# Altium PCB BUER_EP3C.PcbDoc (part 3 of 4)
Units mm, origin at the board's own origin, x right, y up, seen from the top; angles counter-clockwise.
Board outline 150 x 80 mm, 2 copper layers (Top Layer, Bottom Layer), stack 1.571 mm thick; 295 components, 180 nets, 1344 pads, 488 vias.
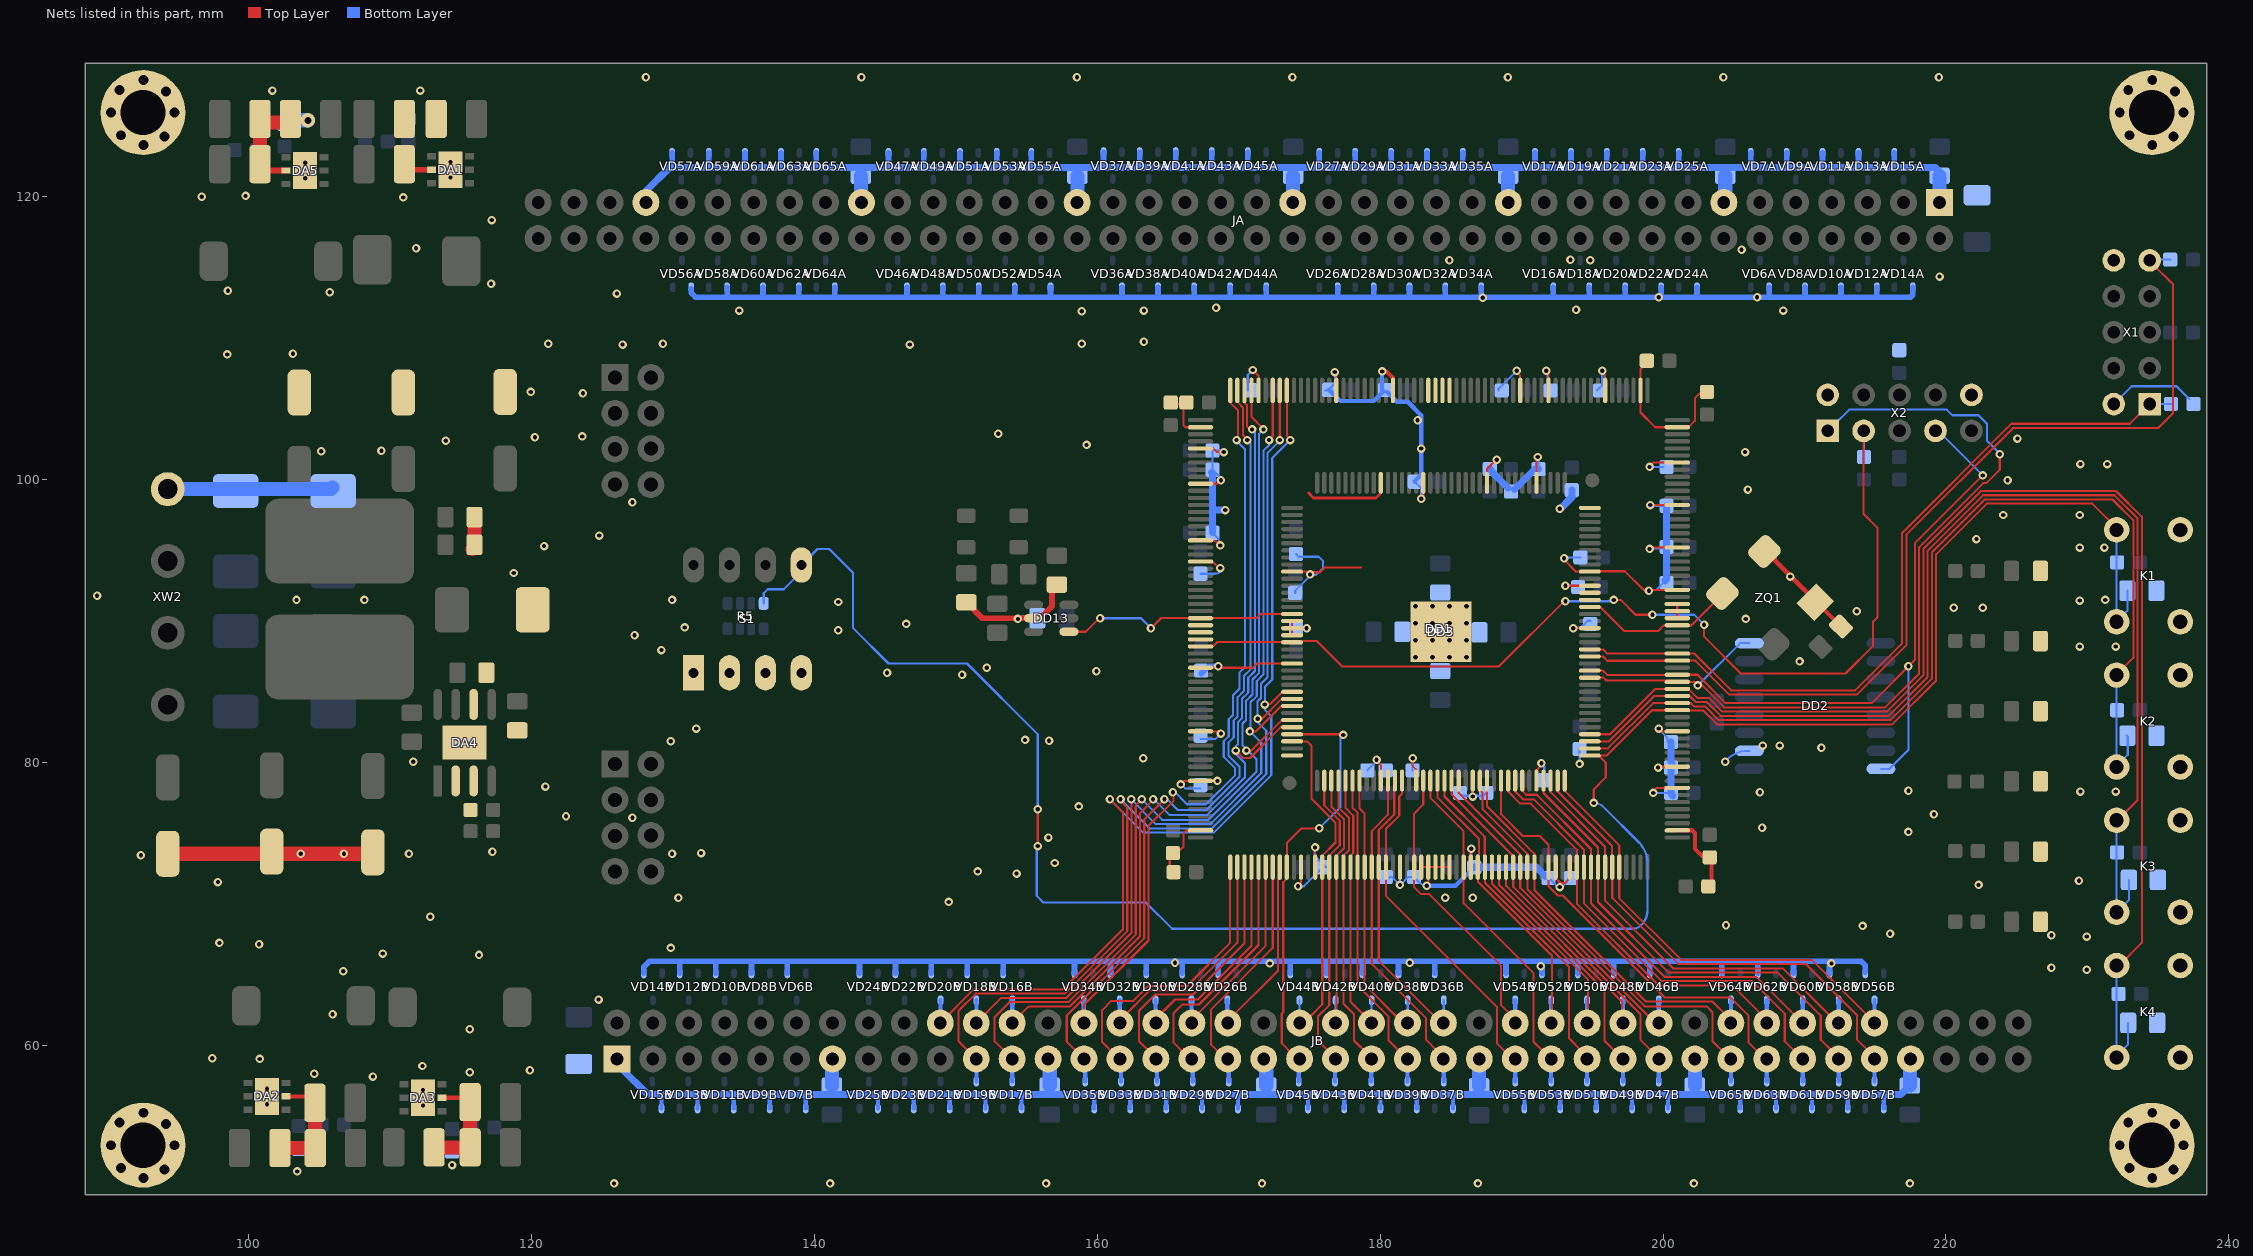
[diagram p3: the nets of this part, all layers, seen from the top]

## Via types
v1: diameter 0.6, hole 0.3, Top Layer to Bottom Layer, tented both sides, 413 vias
v2: diameter 1.4, hole 0.7, Top Layer to Bottom Layer, 32 vias
v3: diameter 1, hole 0.5, Top Layer to Bottom Layer, tented both sides, 19 vias
v4: diameter 0.66, hole 0.33, Top Layer to Bottom Layer, tented top, 16 vias
v5: diameter 0.6, hole 0.3, Top Layer to Bottom Layer, 8 vias

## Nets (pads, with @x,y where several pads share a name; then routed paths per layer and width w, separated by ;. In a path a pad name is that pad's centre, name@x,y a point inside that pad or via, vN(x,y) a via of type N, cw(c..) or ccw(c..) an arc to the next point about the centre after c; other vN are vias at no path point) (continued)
B15: DD1.112 DD3.99 JB.20 VD20B.3 | length 71
  Top Layer w0.15: JB.20@148.91,61.59 151.285,63.965 157.579,63.965 161.825,68.211 161.825,76.475 v1@161,77.3 ; v1@171.9,84.15 172.25,84.15 173.1,85 DD3.99@173.775,85 ; DD1.112@173.406,106.307 173.406,103.094 v1@173.7,102.8
  Bottom Layer w0.15: v1@160.925,77.375 163.25,75.05 168.238,75.05 172.3,79.112 172.3,83.278 171.875,83.703 171.875,85.375 172.375,85.875 172.375,101.525 v1(173.65,102.8)
  Bottom Layer w0.3: JB.20@148.85,61.75 148.925,61.825 VD20B.3@148.925,63.2
  other v1: 160.9,77.4 171.85,84.1
B16: DD1.113 DD3.100 JB.21 VD19B.3 | length 72.9
  Top Layer w0.15: JB.21@151.45,59.05 150.2,60.3 150.2,62.45 151.415,63.665 157.703,63.665 162.125,68.087 162.125,76.825 161.75,77.2 v1@161.75,77.4 ; v1(171.35,83.1) 171.65,83.1 173.05,84.5 DD3.100@173.775,84.5 ; v1@172.906,102.856 DD1.113@172.906,106.307
  Bottom Layer w0.15: v1@161.7,77.35 163.7,75.35 168.113,75.35 171.95,79.187 171.95,82.253 171.325,82.878 171.325,84.317 171.575,84.567 171.575,85.575 172.05,86.05 172.05,101.9 172.9,102.75 v1(172.9,102.8)
  Bottom Layer w0.3: VD19B.3@151.462,57.45 151.462,58.862 JB.21@151.6,59
  other v1: 161.65,77.4
B17: DD1.114 DD3.101 JB.22 VD18B.3 | length 67.8
  Top Layer w0.15: JB.22@151.45,61.59 153.225,63.365 157.827,63.365 162.425,67.963 162.425,77.425 v1@162.4,77.45 ; v1(170.8,82.2) 171.2,82.2 173,84 DD3.101@173.775,84 ; v1(172.15,102.8) 172.406,103.056 DD1.114@172.406,106.307
  Bottom Layer w0.15: v1(162.4,77.4) 164.15,75.65 167.989,75.65 171.6,79.261 171.6,81.4 170.825,82.175 170.825,84.242 171.275,84.692 171.275,85.752 171.75,86.227 171.75,102.05 172.15,102.45 v1(172.15,102.8)
  Bottom Layer w0.3: VD18B.3@151.463,63.2 151.463,61.687 JB.22@151.5,61.65
B18: DD1.117 DD3.103 JB.23 VD17B.3 | length 69.7
  Top Layer w0.15: JB.23@153.99,59.05 152.75,60.29 152.75,62.012 153.803,63.065 157.952,63.065 162.725,67.838 162.725,76.975 v1(163.15,77.4) ; v1(170.55,80.85) 170.9,80.85 173.05,83 DD3.103@173.775,83 ; DD1.117@170.906,106.307 170.906,104.444 v1@171.75,103.6
  Bottom Layer w0.15: v1(163.15,77.4) 164.6,75.95 167.865,75.95 171.25,79.335 171.25,80.25 170.275,81.225 170.275,82.76 170.525,83.01 170.525,84.366 170.975,84.816 170.975,85.876 171.45,86.351 171.45,103.25 v1(171.75,103.55)
  Bottom Layer w0.3: JB.23@153.75,58.95 154,58.7 VD17B.3@154,57.45
B19: DD1.118 DD3.104 JB.24 VD16B.3 | length 65.3
  Top Layer w0.15: JB.24@154.04,61.59 JB.24@153.99,61.59 155.165,62.765 158.076,62.765 163.025,67.714 163.025,76.425 163.9,77.3 v1@163.9,77.5 ; v1(169.8,80.85) 170.325,80.325 170.799,80.325 172.974,82.5 DD3.104@173.775,82.5 ; DD1.118@170.406,106.307 170.406,105.444 170.6,105.25 170.6,103.75 170.85,103.5 v1@170.9,103.5
  Bottom Layer w0.15: v1@163.9,77.5 165.1,76.3 167.791,76.3 170.45,78.959 170.45,79.95 169.8,80.6 169.8,81.15 169.95,81.3 169.95,82.859 170.225,83.134 170.225,84.49 170.675,84.94 170.675,86.001 171.15,86.476 171.15,103.35 v1(170.95,103.55)
  Bottom Layer w0.3: JB.24@154,61.45 VD16B.3@154,63.2
  other v1: 163.95,77.4
B20: DD1.119 JB.27 VD35B.3 | length 58.7
  Top Layer w0.15: JB.27@159.07,59.05 157.85,60.27 157.85,62.115 163.325,67.59 163.325,75.975 v1@164.7,77.35 ; DD1.119@169.906,106.307 169.906,105.494 170.3,105.1 170.3,103.15 v1@170.6,102.85
  Bottom Layer w0.15: v1@164.8,77.55 165.7,76.65 167.716,76.65 170.05,78.984 170.05,79.724 169.275,80.499 169.275,81.408 169.65,81.783 169.65,82.983 169.925,83.258 169.925,84.615 170.375,85.065 170.375,86.125 170.85,86.6 170.85,102.55 v1(170.6,102.8)
  Bottom Layer w0.3: VD35B.3@159.15,57.45 159.15,59.1 JB.27@159.25,59.2
  other v1: 164.75,77.4
B21: DD1.120 JB.28 VD34B.3 | length 54.9
  Top Layer w0.15: JB.28@159.07,61.59 159.07,62.87 163.625,67.425 163.625,75.525 165.4,77.3 v1@165.4,78 ; DD1.120@169.406,106.307 169.406,105.444 169.95,104.9 v1@169.95,102.75
  Bottom Layer w0.15: v1@165.4,78 166.35,77.05 167.692,77.05 169.75,79.108 169.75,79.6 168.95,80.4 168.95,81.508 169.3,81.858 169.3,83.058 169.6,83.358 169.6,84.75 170.05,85.2 170.05,86.35 170.45,86.75 170.45,102.15 v1@169.85,102.75
  Bottom Layer w0.3: VD34B.3@159.05,63.2 159.05,61.95 JB.28@159.3,61.7
  other v1: 165.35,77.9 169.85,102.8
B22: DD1.181 JB.29 VD33B.3 | length 20.3
  Top Layer w0.15: JB.29@161.25,59.35 160.35,60.25 160.35,62.5 161,63.15 162.55,63.15 163.6,64.2 166.35,64.2 169.4,67.25 DD1.181@169.4,71.95
  Bottom Layer w0.3: VD33B.3@161.687,57.45 161.687,58.537 JB.29@161.7,58.55
B23: DD1.182 JB.30 VD32B.3 | length 17
  Top Layer w0.15: JB.30@161.95,62.15 161.974,62.15 163.724,63.9 166.55,63.9 169.906,67.256 DD1.182@169.906,72.607
  Bottom Layer w0.3: JB.30@161.45,61.7 161.588,61.838 VD32B.3@161.588,63.2
B24: DD1.183 JB.31 VD31B.3 | length 19.6
  Top Layer w0.15: JB.31@163.75,59.5 162.95,60.3 162.95,62.45 164.1,63.6 166.8,63.6 170.406,67.206 DD1.183@170.406,72.607
  Bottom Layer w0.3: JB.31@164.15,58.95 164.225,58.875 VD31B.3@164.225,57.45
B25: DD1.184 JB.32 VD30B.3 | length 15.5
  Top Layer w0.15: JB.32@164.3,62.05 165.5,63.25 167.1,63.25 170.906,67.056 DD1.184@170.906,72.607
  Bottom Layer w0.3: JB.32@164.05,61.95 164.125,62.025 VD30B.3@164.125,63.2
B26: DD1.185 JB.33 VD29B.3 | length 17.7
  Top Layer w0.15: JB.33@166.2,59.4 165.4,60.2 165.4,62.3 166,62.9 167.2,62.9 171.4,67.1 ; 171.406,67.1 DD1.185@171.406,72.607
  Bottom Layer w0.3: JB.33@166.7,58.4 166.762,58.338 VD29B.3@166.762,57.45
B27: DD1.186 JB.34 VD28B.3 | length 13.9
  Top Layer w0.15: JB.34@166.85,62 171.906,67.056 DD1.186@171.906,72.607
  Bottom Layer w0.3: VD28B.3@166.662,63.2 166.662,62.088 JB.34@166.75,62
B28: DD1.187 JB.35 VD27B.3 | length 16.8
  Top Layer w0.15: JB.35@168.8,59.3 168.05,60.05 168.05,62.55 172.406,66.906 DD1.187@172.406,72.607
  Bottom Layer w0.3: JB.35@169.2,58.8 169.3,58.7 VD27B.3@169.3,57.45
B29: DD1.188 JB.36 VD26B.3 | length 13.2
  Top Layer w0.15: JB.36@169.45,61.95 172.781,65.281 172.781,71.731 172.85,71.8 172.85,72.55 DD1.188@172.906,72.607
  Bottom Layer w0.3: VD26B.3@169.2,63.2 169.2,62.2 JB.36@169.25,62.15
B30: DD1.189 DD3.105 JB.39 VD45B.3 | length 29.8
  Top Layer w0.15: DD1.189@173.4,71.85 173.4,71.8 173.15,71.55 173.15,62.35 173.05,62.25 173.05,60.15 JB.39@173.8,59.4 ; DD1.189@173.406,72.607 173.406,74.316 174.441,75.35 v1(175.7,75.35) ; DD3.105@173.775,82 v1@177.35,82
  Bottom Layer w0.15: v1(175.7,75.35) 177.2,76.85 177.2,81.9 v1@177.25,81.95
  Bottom Layer w0.3: JB.39@174,58.95 174.25,58.7 VD45B.3@174.25,57.45
  other v1: 177.4,81.95
B31: DD1.194 DD3.106 JB.40 VD44B.3 | length 22.7
  Top Layer w0.15: JB.40@174.35,62.05 175.05,62.05 175.906,62.906 DD1.194@175.906,72.607 ; DD3.106@174.4,81.5 174.85,81.5 175.15,81.2 175.15,77.45 176.85,75.75 176.85,74.35 DD1.194@175.95,73.45
  Bottom Layer w0.15: JB.40@174.3,61.85 VD44B.3@174.3,63.2
B32: DD1.195 DD3.110 JB.41 VD43B.3 | length 21.3
  Top Layer w0.15: DD3.110@176.05,78.2 176.05,76.974 177.15,75.874 177.15,74.15 DD1.195@176.45,73.45 ; DD1.195@176.406,72.607 176.406,62.856 175.6,62.05 175.6,60.35 JB.41@176.75,59.2
  Bottom Layer w0.3: VD43B.3@176.812,57.45 176.812,58.962 JB.41@176.85,59
B33: DD1.196 DD3.111 JB.42 VD42B.3 | length 17.6
  Top Layer w0.15: DD3.111@176.55,78.1 176.55,76.899 177.45,75.999 177.45,73.95 DD1.196@176.9,73.4 ; JB.42@176.65,61.75 176.906,62.006 DD1.196@176.906,72.607
  Bottom Layer w0.15: VD42B.3@176.85,63.2 176.85,62.1 JB.42@177,61.95
B34: DD1.197 DD3.112 JB.43 VD41B.3 | length 20.9
  Top Layer w0.15: DD3.112@177,78.25 177.05,78.2 177.05,76.85 177.8,76.1 177.8,73.8 DD1.197@177.4,73.4 ; DD1.197@177.5,72.7 DD1.197@177.406,72.607 177.406,62.944 178.15,62.2 178.15,60.35 JB.43@179.15,59.35
  Bottom Layer w0.3: JB.43@179.35,58.9 179.375,58.875 VD41B.3@179.375,57.45
B35: DD1.198 DD3.113 JB.44 VD40B.3 | length 17.8
  Top Layer w0.15: DD3.113@177.55,78.25 177.55,76.8 178.1,76.25 178.1,73.6 DD1.198@177.95,73.45 ; DD1.198@177.906,72.607 177.906,63.094 178.7,62.3 JB.44@179.4,62.3
  Bottom Layer w0.15: VD40B.3@179.4,63.2 179.4,61.85 JB.44@179.45,61.8
B36: DD1.199 DD3.114 JB.45 VD39B.3 | length 21.9
  Top Layer w0.15: DD3.114@178.05,78.25 178.05,76.8 178.406,76.444 DD1.199@178.406,72.607 178.406,64.235 180.6,62.042 180.6,60.35 JB.45@181.7,59.25
  Bottom Layer w0.3: VD39B.3@181.937,57.45 181.937,58.787 JB.45@181.95,58.8
B37: DD1.200 DD3.115 JB.46 VD38B.3 | length 19.4
  Top Layer w0.15: DD3.115@178.55,78.25 178.55,76.75 178.906,76.394 DD1.200@178.906,72.607 178.906,64.294 181.3,61.9 JB.46@181.9,61.9
  Bottom Layer w0.15: VD38B.3@181.95,63.2 181.95,61.95 JB.46@182,61.9
B38: DD1.201 DD3.119 JB.47 VD37B.3 | length 22.4
  Top Layer w0.15: DD3.119@180.55,78.05 180.55,76.3 179.406,75.156 DD1.201@179.406,72.607 179.406,65.775 183.25,61.932 183.25,60.4 JB.47@184.05,59.6
  Bottom Layer w0.3: JB.47@184.45,59 184.5,58.95 VD37B.3@184.5,57.45
B39: DD1.202 DD3.120 JB.48 VD36B.3 | length 20.6
  Top Layer w0.15: DD3.120@181,78.4 181,76.326 179.906,75.232 DD1.202@179.906,72.607 179.906,65.994 JB.48@184.5,61.4
  Bottom Layer w0.15: JB.48@184.5,62 VD36B.3@184.5,63.2
B40: DD1.203 DD3.121 JB.51 VD55B.3 | length 25
  Top Layer w0.15: DD3.121@181.55,78.3 181.55,77.8 181.35,77.6 181.35,76.251 180.406,75.308 DD1.203@180.406,72.607 180.406,70.594 188.25,62.75 188.25,60.15 JB.51@189.25,59.15
  Bottom Layer w0.3: JB.51@189.4,59.15 189.55,59 VD55B.3@189.55,57.45
B41: DD1.207 DD3.124 JB.52 VD54B.3 | length 21.5
  Top Layer w0.15: DD1.207@182.4,73.3 182.4,76.4 183.05,77.05 DD3.124@183.05,78.725 ; DD1.207@182.406,72.607 182.406,71.194 182.9,70.7 183.474,70.7 188.55,65.624 188.55,62.85 JB.52@189.6,61.8
  Bottom Layer w0.3: VD54B.3@189.55,63.2 JB.52@189.55,61.59 189.55,61.55 JB.52@189.6,61.5
B42: DD1.214 DD3.125 JB.53 VD53B.3 | length 23.2
  Top Layer w0.15: DD3.125@183.55,78.725 183.55,77.5 185.9,75.15 DD1.214@185.9,73.1 ; DD1.214@185.906,72.607 185.906,70.044 190.85,65.1 190.85,60.25 JB.53@191.55,59.55
  Bottom Layer w0.3: VD53B.3@192.087,57.45 192.087,58.687 JB.53@192.1,58.7
B43: DD1.216 DD3.126 JB.54 VD52B.3 | length 20.6
  Top Layer w0.15: DD3.126@184.05,78.725 184.05,77.55 187,74.6 187,73.55 186.9,73.45 DD1.216@186.9,73.4 ; DD1.216@186.906,72.607 186.906,71.594 192.15,66.35 JB.54@192.15,62.4
  Bottom Layer w0.3: JB.54@191.8,61.7 192.088,61.988 VD52B.3@192.088,63.2
B44: DD1.217 DD3.127 JB.55 VD51B.3 | length 24.7
  Top Layer w0.15: DD3.127@184.55,78.725 184.55,77.6 187.4,74.75 DD1.217@187.4,72.6 ; DD1.217@187.406,72.607 187.406,71.518 193.35,65.574 193.35,60.5 JB.55@194.25,59.6
  Bottom Layer w0.3: JB.55@194.5,59 194.625,58.875 VD51B.3@194.625,57.45
B45: DD1.218 JB.56 VD50B.3 | length 14.9
  Top Layer w0.15: DD1.218@187.906,72.607 187.906,71.442 194.7,64.649 JB.56@194.7,61.8
  Bottom Layer w0.3: VD50B.3@194.625,63.2 194.625,61.975 JB.56@194.65,61.95
B46: DD1.219 JB.57 VD49B.3 | length 18.1
  Top Layer w0.15: DD1.219@188.406,72.607 188.406,71.366 195.85,63.923 195.85,60.35 JB.57@196.95,59.25
  Bottom Layer w0.3: JB.57@197,58.6 197.162,58.438 VD49B.3@197.162,57.45
B47: DD1.220 JB.58 VD48B.3 | length 15.8
  Top Layer w0.15: DD1.220@188.906,72.607 188.906,71.291 197.1,63.097 JB.58@197.1,61.7
  Bottom Layer w0.3: JB.58@197.1,61.75 197.162,61.813 VD48B.3@197.162,63.2
B48: DD1.221 DD3.128 JB.59 VD47B.3 | length 26.1
  Top Layer w0.15: DD3.128@185.05,78.15 185.05,77.75 189.406,73.394 DD1.221@189.406,72.607 189.406,71.215 198.4,62.221 198.4,60.4 JB.59@199.35,59.45
  Bottom Layer w0.3: JB.59@199.55,58.85 199.7,58.7 VD47B.3@199.7,57.45
B49: DD1.222 DD3.129 JB.60 VD46B.3 | length 23.9
  Top Layer w0.15: DD3.129@185.55,78.725 185.55,77.85 189.9,73.5 DD1.222@189.9,73 ; DD1.222@189.906,72.607 189.906,71.139 199.146,61.9 JB.60@199.65,61.9
  Bottom Layer w0.3: VD46B.3@199.7,63.2 199.7,61.9 JB.60@199.75,61.85
B50: DD1.223 DD3.132 JB.63 VD65B.3 | length 29.7
  Top Layer w0.15: DD3.132@187.05,78.725 187.05,78.05 187.25,77.85 187.25,76.7 190.4,73.55 DD1.223@190.4,73.1 ; DD1.223@190.406,72.607 190.406,71.063 198.705,62.765 203.085,62.765 203.5,62.35 203.5,60.3 JB.63@204.5,59.3
  Bottom Layer w0.3: VD65B.3@204.8,57.45 JB.63@204.8,58.45
B51: DD1.224 DD3.133 JB.64 VD64B.3 | length 27.4
  Top Layer w0.15: DD3.133@187.55,78.725 187.55,76.9 190.9,73.55 DD1.224@190.9,73 ; DD1.224@190.906,72.607 190.906,70.988 198.794,63.1 203.5,63.1 204.5,62.1 JB.64@204.55,62.1
  Bottom Layer w0.3: JB.64@204.75,61.85 204.8,61.9 VD64B.3@204.8,63.2
B52: DD1.226 DD3.135 JB.65 VD63B.3 | length 32
  Top Layer w0.15: DD3.135@188.55,78.3 188.55,76.35 190.1,74.8 191.3,74.8 191.906,74.194 DD1.226@191.906,72.607 191.906,71.251 192.558,70.6 192.9,70.6 200.1,63.4 204.75,63.4 206.05,62.1 206.05,60.2 JB.65@206.95,59.3
  Bottom Layer w0.3: JB.65@207.1,59.1 207.337,58.863 VD63B.3@207.337,57.45
B53: DD1.230 DD3.136 JB.66 VD62B.3 | length 29
  Top Layer w0.15: DD3.136@189.05,78.1 189.05,77.95 189.9,77.1 190.65,77.1 193.906,73.844 DD1.230@193.906,72.607 193.906,70.018 199.674,64.25 204.9,64.25 207.25,61.9 JB.66@207.3,61.9
  Bottom Layer w0.3: VD62B.3@207.337,63.2 207.337,61.863 JB.66@207.6,61.6
B54: DD1.231 DD3.137 JB.67 VD61B.3 | length 32.5
  Top Layer w0.15: DD3.137@189.55,78.725 189.55,77.95 190.1,77.4 190.85,77.4 194.4,73.85 DD1.231@194.4,73.3 ; DD1.231@194.406,72.607 194.406,70.044 199.9,64.55 206.3,64.55 208.6,62.25 208.6,60.3 JB.67@209.7,59.2
  Bottom Layer w0.3: JB.67@209.85,58.55 209.875,58.525 VD61B.3@209.875,57.45
B55: DD1.232 DD3.138 JB.68 VD60B.3 | length 30.8
  Top Layer w0.15: DD3.138@190.05,78.2 190.05,78 190.325,77.725 191.075,77.725 194.906,73.894 194.906,70.044 200.1,64.85 206.6,64.85 209.6,61.85 JB.68@209.85,61.85
  Bottom Layer w0.3: JB.68@209.7,61.45 209.875,61.625 VD60B.3@209.875,63.2
B56: DD1.233 DD3.141 JB.69 VD59B.3 | length 32.8
  Top Layer w0.15: DD3.141@191.55,78.725 191.55,77.85 195.4,74 DD1.233@195.4,73.25 ; DD1.233@195.406,72.607 195.406,70.144 200.4,65.15 208.1,65.15 211.15,62.1 211.15,60.4 JB.69@212.05,59.5
  Bottom Layer w0.3: JB.69@212.3,58.65 212.412,58.538 VD59B.3@212.412,57.45
B57: DD1.234 DD3.142 JB.70 VD58B.3 | length 30.7
  Top Layer w0.15: DD3.142@192.05,78.725 192.05,77.9 195.9,74.05 DD1.234@195.9,73.1 ; DD1.234@195.906,72.607 195.906,70.244 200.7,65.45 208.45,65.45 211.75,62.15 JB.70@212.35,62.15
  Bottom Layer w0.3: JB.70@212.25,61.9 212.412,62.062 VD58B.3@212.412,63.2
B58: DD1.235 DD3.143 JB.71 VD57B.3 | length 34.7
  Top Layer w0.15: DD3.143@192.55,78.725 192.55,77.95 196.4,74.1 DD1.235@196.4,73.1 ; DD1.235@196.406,72.607 196.406,70.444 201.1,65.75 210.1,65.75 213.7,62.15 213.7,60.45 JB.71@214.9,59.25
  Bottom Layer w0.3: VD57B.3@214.95,57.45 214.95,58.55 JB.71@215,58.6
B59: DD1.236 DD3.144 JB.72 VD56B.3 | length 32.1
  Top Layer w0.15: DD3.144@193.05,78.725 193.05,78 196.9,74.15 DD1.236@196.9,73.3 ; DD1.236@196.906,72.607 196.906,70.418 201.275,66.05 210.5,66.05 214.6,61.95 JB.72@214.9,61.95
  Bottom Layer w0.3: VD56B.3@214.95,63.2 214.95,62 JB.72@215.05,61.9
BUT0: C90.1 DD1.19 DD3.1 K1.2 R5.4 R20.1 S1.5 | length 158.9
  Top Layer w0.15: v1@155.8,74 v1(155.8,74.1) v1(155.8,76.7) ; DD3.1@194.825,80.5 DD3.1@195.45,80.5 ; v1@195,77.15 195.1,77.25 195.1,78.1 195.95,78.95 195.95,80 DD3.1@195.45,80.5 ; DD1.19@200.8,83.7 199.223,83.7 196.023,80.5 DD3.1@195.45,80.5 ; DD1.19@201.006,83.707 201.037,83.676 202.845,83.676 203.821,82.7 216.197,82.7 219.3,85.803 219.3,94.727 222.873,98.3 230.35,98.3 K1.2@232.3,96.35
  Bottom Layer w0.15: R5.4@136.425,91.25 136.425,91.975 136.7,92.25 137.85,92.25 138.7,93.1 S1.5@139,93.1 ; S1.5@139.085,93.961 140.224,95.1 141.05,95.1 142.75,93.4 142.75,89.5 145.25,87 150.8,87 155.8,82 v1@155.8,76.75 ; v1(155.8,74.1) 155.725,74.025 155.725,70.575 156.2,70.1 163.45,70.1 165.3,68.25 197.85,68.25 ccw(c197.85,69.095) 198.447,68.497 ; v1@195,77.2 v1@195.3,77.2 ; v1(195.1,77.15) cw(c195.1,76.184) 195.783,76.867 198.299,74.351 cw(c196.848,72.9) 198.9,72.9 198.9,69.586 cw(c197.364,69.586) 198.45,68.5 ; K1.2@231.95,89.75 232.064,89.864 K1.2@232.064,89.95 K1.2@232.064,96.45 ; K1.2@232.4,90.3 232.825,90.725 C90.1@232.825,92.15
BUT1: C91.1 DD1.20 DD3.2 K2.2 R21.1 | length 72
  Top Layer w0.15: DD3.2@194.825,81 196.099,81 199.299,84.2 DD1.20@200.45,84.2 ; DD1.20@201.006,84.207 201.945,84.207 202.176,83.976 202.97,83.976 203.945,83 216.073,83 219,85.927 219,94.851 222.749,98.6 231.774,98.6 233.25,97.124 233.25,87.4 K2.2@232.15,86.3
  Bottom Layer w0.15: K2.2@232.064,86.184 232.064,79.886 K2.2@232.2,79.75 ; K2.2@232.25,79.95 232.85,80.55 232.85,81.825 C91.1@232.775,81.9
BUT2: C92.1 DD1.21 DD3.3 K3.2 R22.1 | length 83.6
  Top Layer w0.15: DD3.3@195.1,81.5 196.174,81.5 199.381,84.707 DD1.21@201.006,84.707 201.869,84.707 202.3,84.276 203.094,84.276 204.07,83.3 215.949,83.3 218.7,86.051 218.7,94.976 222.624,98.9 231.899,98.9 233.55,97.249 233.55,77.35 K3.2@232.1,75.9
  Bottom Layer w0.15: K3.2@232.064,75.917 232.064,69.736 232.223,69.577 232.225,69.575 K3.2@232.25,69.55 ; K3.2@232.15,69.5 232.925,70.275 C92.1@232.925,71.7
BUT3: C93.1 DD1.22 DD3.4 K4.2 R23.1 | length 93.8
  Top Layer w0.15: DD3.4@194.825,82 196.25,82 199.45,85.2 DD1.22@200.55,85.2 ; DD1.22@201.006,85.207 201.793,85.207 202.424,84.576 203.218,84.576 204.194,83.6 215.824,83.6 218.4,86.176 218.4,95.1 222.5,99.2 232.023,99.2 233.85,97.373 233.85,67.25 K4.2@232.2,65.6
  Bottom Layer w0.15: K4.2@232.064,65.65 232.064,59.836 K4.2@232.15,59.75 ; K4.2@232.25,59.45 232.875,60.075 C93.1@232.875,61.6
CLK0: DD1.31 DD3.22 ZQ1.3 | length 9.6
  Top Layer w0.15: DD3.22@195.25,91 195.55,91 197.25,89.3 199.65,89.3 200.05,89.7 DD1.31@200.3,89.7 ; DD1.31@201.006,89.707 202.007,89.707 ZQ1.3@203.9,91.6
CLK1: DD1.149 DD3.88 DD13.4 | length 16.2
  Top Layer w0.15: DD13.4@158,89.25 159.2,89.25 160.15,90.2 v1(160.2,90.2) ; v1(163.8,89.5) 164.507,90.207 DD1.149@167.306,90.207 171.257,90.207 171.55,90.5 DD3.88@173.25,90.5
  Bottom Layer w0.15: v1@160.3,90.2 163.1,90.2 v1(163.8,89.5)
CONFIG_DONE: DD1.153 DD3.92 R14.1 X2.3 | length 70.4
  Top Layer w0.15: DD1.153@167.306,88.207 168.157,88.207 168.475,88.525 173.275,88.525 DD3.92@173.3,88.5 ; DD3.92@173.775,88.5 174.458,88.5 174.558,88.6 175.5,88.6 177.3,86.8 188.4,86.8 v1@193.05,91.45 ; v1(196.523,91.5) 197,91.5 198.05,90.45 v1(199.25,90.45) v1@199.3,90.45 ; v1@202.9,89.8 v1(202.9,89.75) 202.9,88.9 205.5,86.3 212.9,86.3 214.85,88.25 214.85,89.95 215.15,90.25 215.15,96.6 214.18,97.57 X2.3@214.18,103.45
  Bottom Layer w0.15: v1(193.1,91.4) v1@196.45,91.4 ; v1(199.25,90.45) 202.2,90.45 v1@202.85,89.8 ; R14.1@214.2,101.6 214.2,102.95 X2.3@214.25,103
DATA: DD1.24 DD2.8 DD3.13 X2.7 | length 52.6
  Top Layer w0.15: DD3.13@194.825,86.5 195.75,86.5 196.05,86.2 DD1.24@200.5,86.2 ; DD1.24@201.006,86.207 202.436,86.207 204.442,84.2 214.75,84.2 217.8,87.25 217.8,95.5 v1(222.6,100.3)
  Bottom Layer w0.15: DD2.8@215.4,79.555 216.005,79.555 217.35,80.9 v1(217.35,86.8) ; X2.7@219.35,103.35 219.55,103.35 v1(222.6,100.3)
DCLK: DD1.23 DD2.16 DD3.12 X2.1 | length 61.6
  Top Layer w0.15: DD3.12@194.825,86 195.8,86 196,85.8 200.3,85.8 DD1.23@200.4,85.7 ; DD1.23@201.006,85.707 202.511,85.707 204.318,83.9 215.7,83.9 218.1,86.3 218.1,95.224 222.626,99.75 222.85,99.75 223.8,100.7 v1(223.8,101.8)
  Bottom Layer w0.15: v1(202.45,85.45) 205.445,88.445 DD2.16@206.1,88.445 ; X2.1@212.1,103.9 213.15,104.95 220.05,104.95 220.45,104.55 222.3,104.55 222.9,103.95 222.9,102.75 223.8,101.85 v1(223.8,101.8)
GND: 1.0 2.0 3.0 4.0 C1.2 C2.2 C3.2 C4.2 C5.2 C6.2 C7.2 C8.2 C9.2 C10.2 C11.2 C12.2 C13.2 C14.2 C15.2 C16.2 C17.2 C18.2 C19.2 C20.2 C21.2 C22.2 C23.2 C24.2 C25.2 C26.2 C27.2 C28.2 C29.2 C30.2 C31.2 C32.2 C33.2 C34.2 C35.2 C36A.2 C36B.2 C37A.2 C37B.2 C38A.2 C38B.2 C39A.2 C39B.2 C40A.2 C40B.2 C41A.2 C41B.2 C42.2 C43.2 C44.2 C45.2 C46.2 C47.2 C48.2 C49.2 C50.2 C51.2 C52.2 C53.2 C54.2 C55.2 C56.2 C57.2 C58.2 C59.2 C61.2 C62.2 C63.2 C64.2 C65.2 C66.2 C67.2 C68.2 C69.2 C70.2 C71.2 C72.2 C73.2 C74.2 C75.2 C76.2 C77.2 C78.2 C79.2 C80.2 C81.2 C82.2 C83.2 C84.2 C85.2 C86.2 C87.2 C88.2 C89.2 C90.2 C91.2 C92.2 C93.2 DA1.2 DA1.7 DA2.2 DA2.7 DA3.2 DA3.7 DA4.2 DA4.3 DA4.6 DA4.9 DA5.2 DA5.7 DD1.2 DD1.8 DD1.11 DD1.16 DD1.32 DD1.33 DD1.34 DD1.36 DD1.42 DD1.48 DD1.54 DD1.59 DD1.62 DD1.67 DD1.75 DD1.79 DD1.89 DD1.90 DD1.91 DD1.92 DD1.97 DD1.105 DD1.116 DD1.122 DD1.125 DD1.130 DD1.138 DD1.141 DD1.150 DD1.151 DD1.152 DD1.156 DD1.165 DD1.172 DD1.179 DD1.191 DD1.193 DD1.205 DD1.208 DD1.209 DD1.210 DD1.211 DD1.212 DD1.215 DD1.227 DD1.229 DD2.10 DD3.19 DD3.23 DD3.24 DD3.25 DD3.27 DD3.36 DD3.41 DD3.48 DD3.57 DD3.63 DD3.82 DD3.89 DD3.90 DD3.91 DD3.95 DD3.108 DD3.118 DD3.123 DD3.131 DD3.140 DD3.145 DD13.2 JA.1 JA.13 JA.25 JA.37 JA.49 JA.61 JA.73 JB.1 JB.13 JB.25 JB.37 JB.49 JB.61 JB.73 K1.1 K2.1 K3.1 K4.1 LED1.K LED2.K LED3.K LED4.K LED5.K LED6.K R4.2 R7.1 R9.1 R11.1 R13.1 R16.1 R18.1 S1.1 S1.2 S1.3 S1.4 VD3.1 VD4.1 VD5.1 VD6A.1 VD6B.1 VD7A.1 VD7B.1 VD8A.1 VD8B.1 VD9A.1 VD9B.1 VD10A.1 VD10B.1 VD11A.1 VD11B.1 VD12A.1 VD12B.1 VD13A.1 VD13B.1 VD14A.1 VD14B.1 VD15A.1 VD15B.1 VD16A.1 VD16B.1 VD17A.1 VD17B.1 VD18A.1 VD18B.1 VD19A.1 VD19B.1 VD20A.1 VD20B.1 VD21A.1 VD21B.1 VD22A.1 VD22B.1 VD23A.1 VD23B.1 VD24A.1 VD24B.1 VD25A.1 VD25B.1 VD26A.1 VD26B.1 VD27A.1 VD27B.1 VD28A.1 VD28B.1 VD29A.1 VD29B.1 VD30A.1 VD30B.1 VD31A.1 VD31B.1 VD32A.1 VD32B.1 VD33A.1 VD33B.1 VD34A.1 VD34B.1 VD35A.1 VD35B.1 VD36A.1 VD36B.1 VD37A.1 VD37B.1 VD38A.1 VD38B.1 VD39A.1 VD39B.1 VD40A.1 VD40B.1 VD41A.1 VD41B.1 VD42A.1 VD42B.1 VD43A.1 VD43B.1 VD44A.1 VD44B.1 VD45A.1 VD45B.1 VD46A.1 VD46B.1 VD47A.1 VD47B.1 VD48A.1 VD48B.1 VD49A.1 VD49B.1 VD50A.1 VD50B.1 VD51A.1 VD51B.1 VD52A.1 VD52B.1 VD53A.1 VD53B.1 VD54A.1 VD54B.1 VD55A.1 VD55B.1 VD56A.1 VD56B.1 VD57A.1 VD57B.1 VD58A.1 VD58B.1 VD59A.1 VD59B.1 VD60A.1 VD60B.1 VD61A.1 VD61B.1 VD62A.1 VD62B.1 VD63A.1 VD63B.1 VD64A.1 VD64B.1 VD65A.1 VD65B.1 VD66.1 VD67.1 X1.2 X1.10 X2.2 X2.10 XW2.1 ZQ1.1 ZQ1.2 | length 759.9
  Top Layer w0.15: 165.1,73.05 cw(c165.04,72.99) 165.125,72.99 C32.2@165.125,72.35 ; C19.2@165.45,105.35 166.1,105.35 166.1,103.85 166.243,103.707 DD1.122@167.306,103.707 ; C20.2@165.7,73.65 166.1,74.05 166.1,75 166.307,75.207 DD1.179@167.306,75.207 ; v1(165.9,78.45) 166.157,78.707 DD1.172@167.306,78.707 ; DD1.165@167.306,82.207 168.593,82.207 v1(168.75,82.05) ; DD1.141@167.306,94.207 167.922,94.207 cw(c167.922,93.672) 168.3,94.05 168.594,93.756 cw(c168.338,93.5) v1@168.7,93.5 ; DD1.138@167.306,95.707 168.03,95.707 cw(c168.03,94.83) v1@168.65,95.45 ; DD1.130@167.306,99.707 168.457,99.707 v1@168.7,99.95 ; DD1.125@167.306,102.207 168.193,102.207 168.45,101.95 v1@169.05,101.95 ; DD1.156@168,86.7 171,86.7 171.3,87 DD3.95@173.775,87 ; v1(171,107.75) 171.406,107.344 DD1.116@171.406,106.307 ; DD3.91@173.75,89 ccw(c173.69,89.06) 173.775,89.06 DD3.90@173.775,89.5 ; DD3.91@173.775,89 DD3.91@174.055,89 ; DD3.82@173.775,93.5 174.8,93.5 v1@175,93.3 ; v1@174.25,71.35 174.406,71.506 DD1.191@174.406,72.607 ; DD3.89@174.488,90 DD3.89@173.775,90 DD3.90@173.775,89.5 ; v1(174.8,89.5) 174.812,89.488 v1@175,89.488 ; v1@174.9,89.5 DD3.90@173.775,89.5 ; v1(175.05,93.3) 175.2,93.45 175.75,93.45 176.1,93.8 178.65,93.8 ; v1@175.275,74.125 175.406,73.994 DD1.193@175.406,72.607 ; DD1.105@176.906,106.307 v1@176.906,107.494 ; v1@179.75,80.1 180.05,79.8 DD3.118@180.05,78.725 ; v1@181.406,71.344 DD1.205@181.406,72.607 ; v1@182.3,80.15 182.3,79.75 182.55,79.5 DD3.123@182.55,78.725 ; v1@182.8,98.6 183.05,98.85 DD3.57@183.05,99.775 ; DD1.208@182.906,72.607 DD1.209@183.406,72.607 ; v1(183.3,71.3) ccw(c183.043,71.557) 183.406,71.557 DD1.209@183.406,72.607 ; DD1.212@184.9,72.6 184.893,72.607 DD1.209@183.406,72.607 ; DD1.215@186.406,72.607 v1@186.406,73.944 ; v1@186.55,77.4 DD3.131@186.55,78.725 ; DD3.48@187.55,99.775 187.55,100.75 v1@188.15,101.35 ; v1@189.6,107.75 189.6,107.633 189.9,107.333 189.9,106.313 DD1.79@189.906,106.307 ; DD3.140@191.05,78.725 191.05,79.45 v1@191.45,79.85 ; DD3.41@191.05,99.775 v1@191.05,101.55 ; v1@191.7,107.7 191.906,107.494 DD1.75@191.906,106.307 ; DD1.227@192.406,72.607 192.406,71.826 192.751,71.482 193.062,71.482 193.45,71.87 DD1.229@193.45,72 ; v1@192.9,94.45 193.85,93.5 DD3.27@194.825,93.5 194.85,93.525 197.301,93.525 198.626,92.2 DD1.36@200.3,92.2 ; v1(193.1,92.5) DD3.25@194.825,92.5 ; v1(193.65,89.5) DD3.19@194.825,89.5 ; v1@195.7,107.6 195.906,107.394 DD1.67@195.906,106.307 ; C25.2@198.95,108.15 198.75,108.15 198.406,107.806 DD1.62@198.406,106.307 198.406,104.744 199.45,103.7 DD1.59@200.4,103.7 ; v1@198.957,98.207 DD1.48@201.006,98.207 ; v1@199,100.9 199.307,101.207 DD1.54@201.006,101.207 ; v1@199.05,95.15 199.107,95.207 DD1.42@201.006,95.207 ; v1@199.25,77.9 199.557,78.207 DD1.8@201.006,78.207 ; v1@199.457,79.707 DD1.11@201.006,79.707 ; v1@199.65,82.4 199.843,82.207 DD1.16@201.006,82.207 ; DD1.32@201,90.2 DD1.32@201.006,90.207 DD1.33@201.006,90.707 DD1.34@201.006,91.207 ; DD1.59@201.006,103.707 201.807,103.707 202.25,104.15 202.25,105.75 C18.2@202.8,106.3
  Top Layer w0.2: 174.95,99.05 175.3,98.7 179.7,98.7 180.05,99.05 DD3.63@180.05,99.775
  Top Layer w0.3: DA2.2@102.65,56.4 C52.2@104.55,56.4 ; DA3.2@113.68,56.3 C56.2@115.2,56.3 ; v1@180.1,107.65 180.45,107.65 180.906,107.193 DD1.97@180.906,106.307 ; DD1.2@201.006,75.207 202.068,75.207 202.25,75.025 202.25,73.9 202.75,73.4 C17.2@202.8,73.4 ; C21.2@203.425,71.25 203.425,72.875 C17.2@203.5,72.95 ; ZQ1.2@207.9,94.6 207.9,94.3 C58.2@212.575,89.625
  Top Layer w0.4: C44.2@100.9,121.9 100.95,121.85 DA5.2@102.67,121.85 ; C35.2@110.9,122.05 111.05,121.9 DA1.2@112.95,121.9 ; C84.2@150.75,91.325 151.875,90.2 v1@154.3,90.2 ; v1@154.35,90.15 154.4,90.2 DD13.2@155.5,90.2 155.95,90.2 156.8,91.05 C83.2@156.8,92.35
  Top Layer w1: C59.2@94.3,73.55 108.45,73.55 C66.2@108.65,73.75 ; C44.2@100.825,122.3 100.825,124.875 C43.2@100.9,124.95 ; C43.2@100.95,125.25 102.725,125.25 C42.2@102.975,125.5 ; C51.2@102.225,52.75 104.5,52.75 C53.2@104.55,52.7 ; C53.2@104.7,53.2 C52.2@104.7,55.95 ; C54.2@113.125,52.8 C55.2@115.5,52.8 ; C55.2@115.25,52.55 C55.2@115.5,52.8 ; C55.2@115.65,52.7 115.55,52.8 C55.2@115.5,52.8 ; C56.2@115.675,56 115.675,52.975 C55.2@115.5,52.8 ; C65.2@115.85,95.1 115.975,95.225 C65.2@115.975,95.4 C64.2@115.975,97.35
  Bottom Layer w0.15: v1@165.95,78.45 166.225,78.175 C8.2@167.3,78.175 ; C22.2@167.3,81.675 168.375,81.675 v1@168.8,82.1 ; C31.2@167.3,93.35 168.338,93.35 ccw(c168.338,93.862) v1@168.7,93.5 ; C10.2@168.15,96.25 168.473,95.927 cw(c168.046,95.5) v1@168.65,95.5 ; v1@168.7,99.95 ccw(c168.217,99.95) 168.559,100.291 C30.2@168.15,100.7 C9.2@168.15,102.05 168.95,102.05 v1@169.05,101.95 ; C28.2@170.645,106.315 170.645,107.395 v1(171,107.75) ; C74.2@174,92 174,92.15 175.05,93.2 v1(175.05,93.3) ; C73.2@174.05,89.45 v1@174.9,89.45 ; C81.2@174.05,94.75 174.25,94.55 175.65,94.55 175.975,94.225 175.975,93.783 175.442,93.25 v1@175.2,93.25 ; v1(174.2,71.25) 174.6,71.25 C13.2@175.7,72.35 ; v1@175.35,74 175.35,73.425 C13.2@176.175,72.6 ; C11.2@176.125,106.3 176.3,106.3 176.8,106.8 176.8,107.45 176.75,107.5 v1@176.75,107.6 ; C75.2@179.1,79.45 179.75,80.1 C72.2@180,79.85 ; C23.2@180.65,71.85 180.7,71.9 180.85,71.9 181.412,71.338 181.975,71.9 C15.2@182.4,71.9 182.788,71.512 ccw(c183.3,72.024) v1(183.3,71.3) ; C69.2@182.3,79.45 v1@182.3,80.2 ; C50.2@182.45,99.85 182.9,99.4 v1(182.9,98.65) ; C70.2@185.8,77.7 185.85,77.65 187.3,77.65 C76.2@187.5,77.85 ; v1@186.45,73.85 186.45,72.8 C14.2@186.65,72.6 ; C6.2@188.375,106.3 188.375,106.425 189.55,107.6 v1@189.65,107.6 ; v1@189.55,107.85 189.65,107.75 v1(189.65,107.7) ; v1(191.15,101.6) 191.2,101.55 C48.2@191.2,100.75 ; v1@191.45,79.85 191.6,79.7 C71.2@191.6,78.75 ; v1@191.8,107.6 191.825,107.575 C27.2@191.825,106.3 ; C16.2@191.9,71.85 192.7,71.05 193.2,71.55 C82.2@193.2,71.6 ; v1@192.9,94.5 C78.2@194.15,94.5 ; v1(193.1,92.5) C46.2@193.825,92.5 ; v1@193.65,89.55 194.2,89.55 194.675,90.025 C45.2@194.85,90.025 ; v1(194.1,79.9) C77.2@194.1,80.95 ; C5.2@195.325,106.3 195.7,106.675 v1@195.7,107.6 ; v1(199.05,100.9) C26.2@200.025,100.9 ; v1@199.1,92.2 199.525,92.2 C3.2@200.025,92.7 ; v1@199.1,95.15 199.925,95.15 C24.2@200.025,95.25 ; v1@199.15,98.2 199.2,98.15 C4.2@200.025,98.15 ; v1@199.25,77.85 v1(199.3,77.85) C1.2@200.275,77.85 ; v1(199.65,79.65) C47.2@200.25,79.65 ; v1@199.65,82.4 200.325,81.725 C2.2@200.325,81.45 ; v1@204.5,80.2 cw(c206.009,78.691) 206.009,80.825 DD2.10@206.1,80.825 ; X1.2@231.86,105.34 233.12,106.6 236.3,106.6 R4.2@237.2,105.7
  Bottom Layer w0.3: 129.15,56.5 129.2,56.45 VD15B.1@129.2,55.55 ; VD13B.1@131.75,55.55 131.75,56.4 131.8,56.45 ; VD11B.1@134.3,55.55 134.3,56.5 134.35,56.55 ; VD9B.1@136.85,55.55 136.85,56.5 ; VD7B.1@139.4,55.55 139.4,56.4 139.45,56.45 ; VD25B.1@144.5,55.55 144.5,56.55 144.55,56.6 ; 147,56.55 147.037,56.513 VD23B.1@147.037,55.55 ; VD21B.1@149.575,55.55 149.575,56.525 149.6,56.55 ; 152.1,56.5 152.112,56.488 VD19B.1@152.112,55.55 ; VD17B.1@154.65,55.55 154.65,56.5 ; 159.75,56.5 159.8,56.45 VD35B.1@159.8,55.55 ; VD33B.1@162.337,55.55 162.337,56.437 162.4,56.5 ; VD31B.1@164.875,55.55 164.875,56.275 165,56.4 ; 167.35,56.55 167.412,56.488 VD29B.1@167.412,55.55 ; VD27B.1@169.95,55.55 169.95,56.45 ; VD45B.1@174.9,55.55 174.9,56.35 174.95,56.4 ; C11.2@176.4,106.35 177.2,105.55 179.55,105.55 C12.2@180.25,106.25 ; VD43B.1@177.463,55.55 177.463,56.312 177.6,56.45 ; VD41B.1@180.025,55.55 180.025,56.55 180.025,56.575 180.05,56.6 ; C12.2@180.127,106.343 180.127,107.577 v1@180.2,107.65 ; C12.2@180.5,106.2 181.2,105.5 181.95,105.5 182.9,104.55 182.9,100.35 182.45,99.9 C50.2@182.45,99.85 ; VD39B.1@182.587,55.55 182.587,56.537 182.6,56.55 182.65,56.6 ; v1(183.3,71.3) 185.35,71.3 C14.2@186.45,72.4 ; VD37B.1@185.15,55.55 185.15,56.45 185.2,56.5 ; VD55B.1@190.2,55.55 190.2,56.45 190.25,56.5 ; VD53B.1@192.737,55.55 192.737,56.437 192.8,56.5 ; 195.25,56.65 195.275,56.625 195.275,56.55 VD51B.1@195.275,55.55 ; VD49B.1@197.812,55.55 197.812,56.412 197.95,56.55 ; VD47B.1@200.35,55.55 200.35,56.55 ; VD65B.1@205.45,55.55 205.45,56.45 205.55,56.55 ; VD63B.1@207.987,55.55 207.987,56.437 208.1,56.55 ; 210.35,56.5 210.525,56.325 VD61B.1@210.525,55.55 ; 213,56.55 213.062,56.488 VD59B.1@213.062,55.55 ; VD57B.1@215.6,55.55 215.6,56.5
  Bottom Layer w0.4: VD14B.1@127.95,65.1 127.95,65.55 128.35,65.95 214,65.95 214.3,65.65 VD56B.1@214.3,65.2 ; 129.95,122.05 VD57A.1@129.95,123.1 ; VD12B.1@130.487,65.1 130.487,65.837 130.5,65.85 ; VD56A.1@131.3,113.5 131.3,113.2 131.6,112.9 217.5,112.9 217.65,113.05 VD14A.1@217.65,113.6 ; 132.5,122.15 132.55,122.2 VD59A.1@132.55,123.1 ; 133,65.85 133.025,65.825 VD10B.1@133.025,65.1 ; VD58A.1@133.837,113.6 133.837,113.012 133.85,113 ; 135.1,122.05 VD61A.1@135.1,123.1 ; 135.55,65.9 135.562,65.888 VD8B.1@135.562,65.1 ; 136.35,113.05 136.375,113.075 VD60A.1@136.375,113.6 ; VD63A.1@137.65,123.1 137.65,122.25 137.7,122.2 ; VD6B.1@138.1,65.1 138.1,65.85 ; 138.9,113 138.912,113.012 VD62A.1@138.912,113.6 ; VD65A.1@140.15,123.1 140.15,122.1 140.2,122.05 ; 141.45,113 VD64A.1@141.45,113.6 ; VD24B.1@143.2,65.1 143.2,65.85 ; 145.25,122.1 VD47A.1@145.25,123.1 ; 145.7,65.85 145.737,65.813 VD22B.1@145.737,65.1 ; 146.55,113 VD46A.1@146.55,113.6 ; VD49A.1@147.75,123.1 147.75,122.05 147.8,122 ; 148.25,65.9 148.275,65.875 VD20B.1@148.275,65.1 ; VD48A.1@149.087,113.6 149.087,113.062 149.1,113.05 ; 150.3,122.15 VD51A.1@150.3,123.1 ; 150.8,65.9 150.812,65.888 VD18B.1@150.812,65.1 ; 151.625,113.075 VD50A.1@151.625,113.6 ; 152.9,122.15 VD53A.1@152.9,123.1 ; VD16B.1@153.35,65.1 153.35,65.85 ; VD52A.1@154.162,113.6 154.162,112.988 154.2,112.95 ; v1@154.45,90.15 154.5,90.2 C85.2@155.775,90.2 ; 155.35,122.15 VD55A.1@155.35,123.1 ; 156.7,113 VD54A.1@156.7,113.6 ; VD34B.1@158.4,65.1 158.4,65.9 ; 160.45,122.05 VD37A.1@160.45,123.15 ; 160.9,65.85 160.937,65.813 VD32B.1@160.937,65.1 ; 161.75,112.95 VD36A.1@161.75,113.6 ; 163,122.15 VD39A.1@163,123.15 ; 163.45,65.9 163.475,65.875 VD30B.1@163.475,65.1 ; 164.25,112.95 164.3,113 VD38A.1@164.3,113.6 ; 165.55,122.3 VD41A.1@165.55,123.15 ; 166,65.9 166.012,65.888 VD28B.1@166.012,65.1 ; 166.85,112.95 VD40A.1@166.85,113.6 ; C7.2@167.35,86.275 167.875,86.8 v1(168.55,86.8) v1@168.6,86.8 ; 168.05,122.15 168.1,122.2 VD43A.1@168.1,123.15 ; 168.5,65.85 168.55,65.8 VD26B.1@168.55,65.1 ; VD42A.1@169.4,113.6 169.4,113 169.45,112.95 ; 170.65,122.15 VD45A.1@170.65,123.15 ; 171.95,113.05 VD44A.1@171.95,113.6 ; VD44B.1@173.65,65.1 173.65,65.85 ; 175.6,122 175.65,122.05 175.7,122.1 VD27A.1@175.7,123.1 ; VD42B.1@176.2,65.1 176.2,65.85 ; 177,113 VD26A.1@177,113.6 ; VD29A.1@178.237,123.1 178.237,122.163 178.25,122.15 ; VD40B.1@178.75,65.1 178.75,65.85 ; VD28A.1@179.537,113.6 179.537,112.962 179.55,112.95 ; VD31A.1@180.775,123.1 180.775,122.175 180.8,122.15 ; VD38B.1@181.3,65.1 181.3,65.85 ; 182.05,112.95 182.075,112.975 VD30A.1@182.075,113.6 ; VD33A.1@183.312,123.1 183.312,122.188 183.35,122.15 ; VD36B.1@183.85,65.1 183.85,65.85 ; VD32A.1@184.612,113.6 184.612,113.038 184.65,113 ; 185.8,122.15 185.85,122.2 VD35A.1@185.85,123.1 ; v1@187.15,113 VD34A.1@187.15,113.6 ; VD54B.1@188.9,65.1 188.9,65.85 ; 190.95,122.1 VD17A.1@190.95,123.1 ; 191.4,65.9 191.437,65.863 VD52B.1@191.437,65.1 ; 192.2,112.95 192.25,113 VD16A.1@192.25,113.6 ; 193.45,122.05 193.487,122.087 VD19A.1@193.487,123.1 ; VD50B.1@193.975,65.1 193.975,65.875 194,65.9 ; 194.75,113 194.787,113.038 VD18A.1@194.787,113.6 ; VD21A.1@196.025,123.1 196.025,122.175 196.05,122.15 ; 196.5,65.9 196.512,65.888 VD48B.1@196.512,65.1 ; VD20A.1@197.325,113.6 197.325,112.975 197.35,112.95 ; 198.55,122.1 198.562,122.112 VD23A.1@198.562,123.1 ; VD46B.1@199.05,65.1 199.05,65.75 ; v1@199.85,112.95 199.862,112.962 VD22A.1@199.862,113.6 ; 201.05,122.2 201.1,122.25 VD25A.1@201.1,123.1 ; 202.35,113 202.4,113.05 VD24A.1@202.4,113.6 ; VD64B.1@204.15,65.1 204.15,65.9 ; 206.15,122.05 206.2,122.1 VD7A.1@206.2,123.1 ; VD62B.1@206.687,65.1 206.687,65.787 206.75,65.85 ; 207.5,112.95 VD6A.1@207.5,113.6 ; VD9A.1@208.737,123.1 208.737,122.213 208.75,122.2 ; VD60B.1@209.225,65.1 209.225,65.825 209.25,65.85 ; VD8A.1@210.037,113.6 210.037,112.962 210.05,112.95 ; 211.25,122.1 211.275,122.125 VD11A.1@211.275,123.1 ; v1@211.75,65.9 211.762,65.888 VD58B.1@211.762,65.1 ; 212.55,113 212.575,113.025 VD10A.1@212.575,113.6 ; 213.8,122.1 213.812,122.112 VD13A.1@213.812,123.1 ; 215.1,113 215.112,113.012 VD12A.1@215.112,113.6 ; 216.3,122.15 216.35,122.2 VD15A.1@216.35,123.1
  Bottom Layer w0.5: JB.1@126.35,58.4 128.2,56.55 134.35,56.55 144.5,56.55 147,56.55 149.6,56.55 167.35,56.55 180.025,56.55 182.6,56.55 195.275,56.55 197.95,56.55 200.35,56.55 205.55,56.55 208.1,56.55 213,56.55 216.825,56.55 C41B.2@217.45,57.175 ; JA.73@128.1,119.59 128.1,120.4 129.75,122.05 129.95,122.05 135.1,122.05 140.2,122.05 147.75,122.05 160.45,122.05 175.65,122.05 193.45,122.05 206.15,122.05 219.25,122.05 C36A.2@219.75,121.55 ; C30.2@168.1,100.5 168.15,100.45 168.15,97.85 ; C10.2@168.15,96.25 168.15,97.85 ; v1@168.95,97.85 168.15,97.85 ; C14.2@186.65,72.6 191.05,72.6 C16.2@191.7,71.95 ; C49.2@187.75,100.75 187.75,100.7 C80.2@189.05,99.4 ; C80.2@189.5,99.3 190.95,100.75 C48.2@191.2,100.75 ; v1@192.7,97.9 193.55,98.75 C79.2@193.55,99.25 ; C3.2@200.15,92.85 200.25,92.95 C24.2@200.25,95.25 C4.2@200.25,98.15 ; C47.2@200.55,79.65 C1.2@200.55,77.85 200.55,77.8 C1.2@200.7,77.65 ; C2.2@200.55,81.45 200.55,80 C47.2@200.65,79.9
  Bottom Layer w1: XW2.1@94.3,99.33 105.83,99.33 VD4.1@105.95,99.45 ; R18.1@102.55,125.375 102.575,125.4 v3(104.2,125.4) ; JB.13@141.05,59.05 141.25,58.85 C36B.2@141.25,57.175 ; C41A.2@143.3,121.475 143.3,120.05 JA.61@143.5,119.85 ; C37B.2@156.65,57.175 156.65,58.7 JB.25@156.75,58.8 ; JA.49@158.55,119.5 158.6,119.55 C40A.2@158.6,121.475 ; JB.37@171.7,58.6 171.95,58.35 C38B.2@171.95,57.175 ; C39A.2@173.85,121.475 173.85,119.9 JA.37@174.05,119.7 ; C39B.2@187,57.125 187,58.9 JB.49@187.1,59 ; C38A.2@189.05,121.475 189.05,119.8 JA.25@189.1,119.75 ; JB.61@202.1,58.8 202.25,58.65 C40B.2@202.25,57.175 ; JA.13@204.25,119.7 204.4,119.85 C37A.2@204.4,121.475 ; C41B.2@217.45,57.175 217.45,58.75 JB.73@217.55,58.85 ; C36A.2@219.55,121.475 219.55,120.05 JA.1@219.7,119.9
  other v1: 125.85,50.25 141.117,50.25 156.383,50.25 171.65,50.25 186.917,50.25 202.183,50.25 217.45,50.25 103.45,51.1 114.4,51.55 108.8,57.8 104.65,58 115.65,58.1 119.9,58.25 112.3,58.55 100.8,59.05 97.45,59.1 115.65,61.15 105.95,62.2 124.75,63.25 106.7,65.25 229.95,65.35 227.45,65.5 191.35,65.6 172.2,65.8 211.9,65.8 165.5,65.85 182.1,65.85 116.3,66.4 109.5,66.5 129.85,66.9 100.75,67.15 97.95,67.25 229.95,67.7 227.45,67.8 216.05,67.9 214.1,68.45 204.45,68.5 112.85,69.1 149.5,70.15 130.4,70.45 184.6,70.45 186.55,70.45 192.7,71.2 181.4,71.35 222.3,71.35 97.85,71.55 229.4,71.65 154.3,72.15 151.55,72.3 157,72.9 92.4,73.45 103.7,73.55 106.75,73.55 111.35,73.55 129.95,73.55 132,73.6 117.25,73.7 186.45,73.9 175.4,74 156.55,74.7 217.35,75.1 207,75.4 127.15,76.1 122.45,76.2 219.15,76.35 158.7,76.9 186.55,77.6 206.85,77.9 229.5,77.95 232,77.95 217.35,78 121,78.3 168.5,78.7 191.4,79.95 111.65,80.05 204.4,80.05 179.75,80.2 163.25,80.3 182.3,80.3 211.2,81.05 207.05,81.2 208.25,81.2 129.85,81.5 156.6,81.55 154.9,81.6 131.65,82.4 199.7,82.4 150.45,86.2 145.15,86.35 159.95,86.45 152.2,86.7 209.65,87.15 129.2,87.95 229.45,88.2 232,88.2 127.3,89 141.7,89.35 130.85,89.55 146.5,89.8 154.4,90.15 205.85,90.15 213.7,90.7 220.55,90.95 222.6,90.95 141.7,91.35 229.45,91.45 103.4,91.5 108.2,91.5 129.95,91.5 231.25,91.5 89.3,91.8 199,92.15 209,93.15 118.75,93.4 168.7,93.75 193,94.45 199.05,95.1 229.45,95.2 231.2,95.2 120.9,95.3 168.7,95.35 222.15,95.8 124.8,96.05 224.05,97.5 229.45,97.5 169.05,97.85 192.7,97.95 199.1,98.2 127.15,98.4 206,99.3 168.75,99.95 224.35,99.95 229.5,101.1 231.4,101.1 188.25,101.4 168.95,101.95 205.8,101.95 105.15,102 109.4,102.05 182.9,102.2 159.25,102.45 113.95,102.75 225.05,102.9 120.25,103 123.6,103.05 153,103.25 182.65,104.2 123.65,106.1 119.95,106.2 176.8,107.6 180.15,107.65 191.75,107.7 195.7,107.7 98.5,108.85 103.15,108.9 126.45,109.55 146.75,109.55 121.2,109.6 129.3,109.6 158.9,109.6 163.3,109.75 158.9,111.9 134.7,111.95 163.3,111.95 208.5,111.95 193.85,112 168.4,112.15 187.25,112.85 199.7,112.9 206.65,112.9 126.05,113.15 105.75,113.25 98.55,113.35 117.15,113.85 219.55,114.35 184.9,115.5 194.85,115.5 193.45,115.55 205.55,116.25 111.85,116.35 117.2,118.35 110.95,119.95 96.7,120 99.8,120.05 101.7,127.5 112.15,127.5 128.1,128.45 143.333,128.45 158.567,128.45 173.8,128.45 189.033,128.45 204.267,128.45 219.5,128.45
  other v2: 92.581,50.647 234.581,50.647 94.081,51.247 236.081,51.247 90.981,51.347 232.981,51.347 90.281,52.947 94.781,52.947 232.281,52.947 236.781,52.947 94.181,54.447 236.181,54.447 90.881,54.547 232.881,54.547 92.581,55.247 234.581,55.247 92.581,123.647 234.581,123.647 94.081,124.247 236.081,124.247 90.981,124.347 232.981,124.347 90.281,125.947 94.781,125.947 232.281,125.947 236.781,125.947 94.181,127.447 236.181,127.447 90.881,127.547 232.881,127.547 92.581,128.247 234.581,128.247
  other v4: 182.5,87.45 183.7,87.45 184.9,87.45 186.1,87.45 182.5,88.65 183.7,88.65 184.9,88.65 186.1,88.65 182.5,89.85 183.7,89.85 184.9,89.85 186.1,89.85 182.5,91.05 183.7,91.05 184.9,91.05 186.1,91.05
  other v5: 112.34,55.75 101.31,55.85 112.34,56.85 101.31,56.95 104.01,121.3 114.29,121.35 104.01,122.4 114.29,122.45
JTAG.TCK: DD1.27 DD3.16 R4.1 X1.1 | length 53.7
  Top Layer w0.15: DD3.16@194.825,88 195.75,88 196.05,87.7 DD1.27@200.65,87.7 ; DD1.27@201.006,87.707 202.209,87.707 204.815,85.1 213.576,85.1 216.9,88.424 216.9,96.224 224.626,103.95 233,103.95 X1.1@233.85,104.8
  Bottom Layer w0.15: X1.1@234.85,105.25 234.95,105.35 R4.1@235.9,105.35
JTAG.TDI: DD1.26 DD3.15 R1.1 X1.9 | length 67
  Top Layer w0.15: DD3.15@194.825,87.5 195.75,87.5 196.05,87.2 DD1.26@200.4,87.2 ; DD1.26@201.006,87.207 202.284,87.207 204.691,84.8 213.7,84.8 217.2,88.3 217.2,96.1 224.75,103.65 235,103.65 236.05,104.7 236.05,113.8 X1.9@234.65,115.2
  Bottom Layer w0.15: X1.9@234.55,115.6 234.6,115.55 R1.1@235.85,115.55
